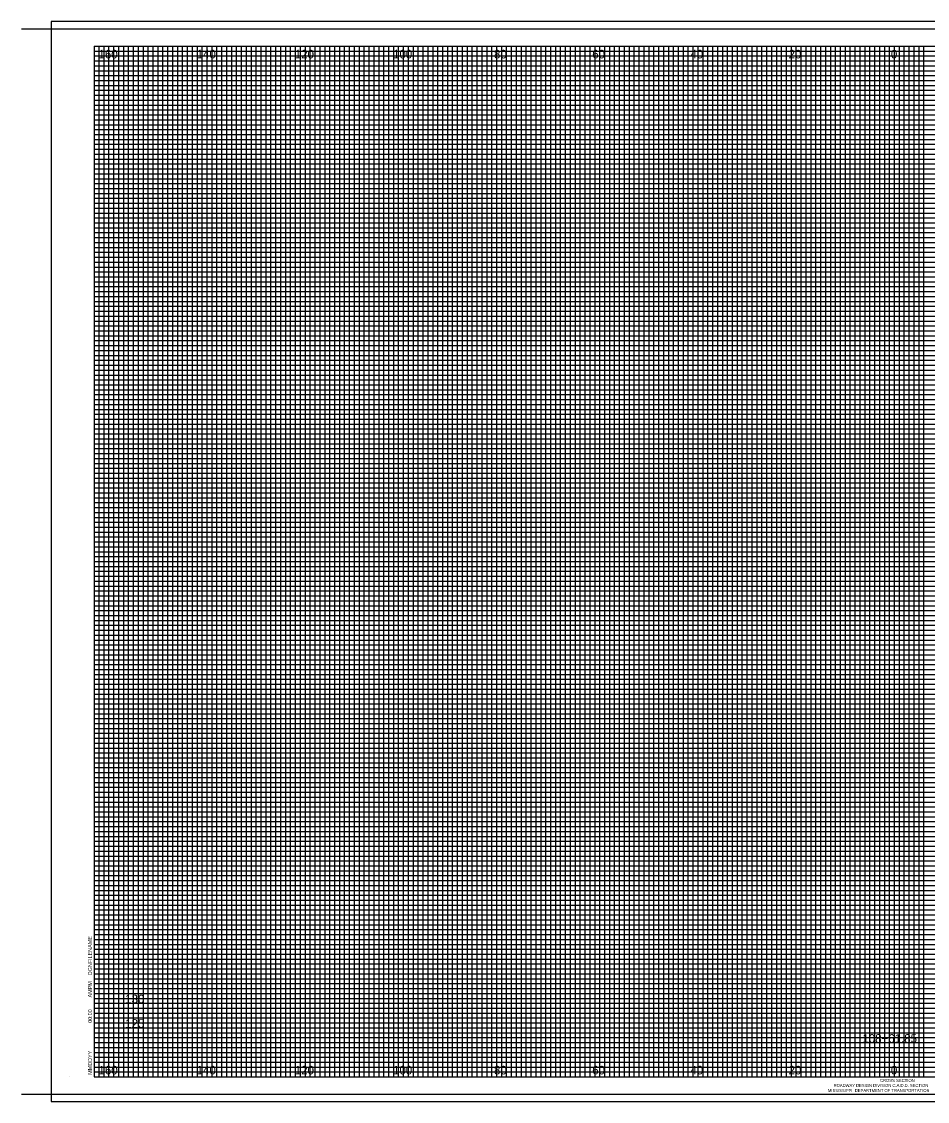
# Model space of a CAD drawing. Extents: x -3604 to 2303, y -13 to 9543.
# Drawn here: x -3604.5 to -3420, y 7604.1 to 7824.1 of the extents above; entities that cross this region are included whole.
import ezdxf

# ---------------------------------------------------------------- set-up
doc = ezdxf.new("R2010")
doc.units = 0
for name, color, linetype in [('SHEET_BORDER', 7, 'Continuous'), ('SHEET_BORDER_TX', 7, 'Continuous'), ('SHEET_DATE_DGN_TX', 7, 'Continuous'), ('SHEET_PLOTTING_SHAPE', 7, 'Continuous'), ('XS_SHEET_LABELS_ELEVATION', 7, 'Continuous'), ('XS_SHEET_LABELS_OFFSET', 7, 'Continuous'), ('XS_SHEET_LABELS_STATION', 7, 'Continuous'), ('XS_SHEET_MAJOR_GRIDS', 7, 'Continuous'), ('XS_SHEET_MEDIUM_GRIDS', 7, 'Continuous'), ('XS_SHEET_MINOR_GRIDS', 7, 'Continuous')]:
    doc.layers.add(name, color=color, linetype=linetype)

msp = doc.modelspace()

# ---------------------------------------------------------------- linework, layer by layer
at = {"layer": 'SHEET_BORDER'}
for p, q in [((-3604.48, 7822.59), (-3252.48, 7822.59)), ((-3589.68, 7819.09), (-3254.68, 7819.09)), ((-3589.68, 7819.09), (-3589.68, 7609.09)), ((-3445.68, 7609.09), (-3445.68, 7819.09)), ((-3594.68, 7609.09), (-3594.68, 7609.09)), ((-3589.68, 7609.09), (-3254.68, 7609.09)), ((-3604.48, 7605.59), (-3252.48, 7605.59))]:
    msp.add_line(p, q, dxfattribs=at)
at = {"layer": 'SHEET_PLOTTING_SHAPE'}
msp.add_lwpolyline([(-3598.48, 7604.09), (-3252.48, 7604.09), (-3252.48, 7824.09), (-3598.48, 7824.09)], close=True, dxfattribs=at)
at = {"layer": 'XS_SHEET_MAJOR_GRIDS'}
for p, q in [((-3584.68, 7609.09), (-3584.68, 7819.09)), ((-3574.68, 7609.09), (-3574.68, 7819.09)), ((-3564.68, 7609.09), (-3564.68, 7819.09)), ((-3554.68, 7609.09), (-3554.68, 7819.09)), ((-3544.68, 7609.09), (-3544.68, 7819.09)), ((-3534.68, 7609.09), (-3534.68, 7819.09)), ((-3524.68, 7609.09), (-3524.68, 7819.09)), ((-3514.68, 7609.09), (-3514.68, 7819.09)), ((-3504.68, 7609.09), (-3504.68, 7819.09)), ((-3494.68, 7609.09), (-3494.68, 7819.09)), ((-3484.68, 7609.09), (-3484.68, 7819.09)), ((-3474.68, 7609.09), (-3474.68, 7819.09)), ((-3464.68, 7609.09), (-3464.68, 7819.09)), ((-3454.68, 7609.09), (-3454.68, 7819.09)), ((-3444.68, 7609.09), (-3444.68, 7819.09)), ((-3434.68, 7609.09), (-3434.68, 7819.09)), ((-3424.68, 7609.09), (-3424.68, 7819.09)), ((-3589.68, 7809.09), (-3254.68, 7809.09)), ((-3589.68, 7799.09), (-3254.68, 7799.09)), ((-3589.68, 7789.09), (-3254.68, 7789.09)), ((-3589.68, 7779.09), (-3254.68, 7779.09)), ((-3589.68, 7769.09), (-3254.68, 7769.09)), ((-3589.68, 7759.09), (-3254.68, 7759.09)), ((-3589.68, 7749.09), (-3254.68, 7749.09)), ((-3589.68, 7739.09), (-3254.68, 7739.09)), ((-3589.68, 7729.09), (-3254.68, 7729.09)), ((-3589.68, 7719.09), (-3254.68, 7719.09)), ((-3589.68, 7709.09), (-3254.68, 7709.09)), ((-3589.68, 7699.09), (-3254.68, 7699.09)), ((-3589.68, 7689.09), (-3254.68, 7689.09)), ((-3589.68, 7679.09), (-3254.68, 7679.09)), ((-3589.68, 7669.09), (-3254.68, 7669.09)), ((-3589.68, 7659.09), (-3254.68, 7659.09)), ((-3589.68, 7649.09), (-3254.68, 7649.09)), ((-3589.68, 7639.09), (-3254.68, 7639.09)), ((-3589.68, 7629.09), (-3254.68, 7629.09)), ((-3589.68, 7619.09), (-3254.68, 7619.09))]:
    msp.add_line(p, q, dxfattribs=at)
at = {"layer": 'XS_SHEET_MEDIUM_GRIDS'}
for p, q in [((-3579.68, 7609.09), (-3579.68, 7819.09)), ((-3569.68, 7609.09), (-3569.68, 7819.09)), ((-3559.68, 7609.09), (-3559.68, 7819.09)), ((-3549.68, 7609.09), (-3549.68, 7819.09)), ((-3539.68, 7609.09), (-3539.68, 7819.09)), ((-3529.68, 7609.09), (-3529.68, 7819.09)), ((-3519.68, 7609.09), (-3519.68, 7819.09)), ((-3509.68, 7609.09), (-3509.68, 7819.09)), ((-3499.68, 7609.09), (-3499.68, 7819.09)), ((-3489.68, 7609.09), (-3489.68, 7819.09)), ((-3479.68, 7609.09), (-3479.68, 7819.09)), ((-3469.68, 7609.09), (-3469.68, 7819.09)), ((-3459.68, 7609.09), (-3459.68, 7819.09)), ((-3449.68, 7609.09), (-3449.68, 7819.09)), ((-3439.68, 7609.09), (-3439.68, 7819.09)), ((-3429.68, 7609.09), (-3429.68, 7819.09)), ((-3589.68, 7814.09), (-3281.68, 7814.09)), ((-3589.68, 7804.09), (-3254.68, 7804.09)), ((-3589.68, 7794.09), (-3254.68, 7794.09)), ((-3589.68, 7784.09), (-3254.68, 7784.09)), ((-3589.68, 7774.09), (-3254.68, 7774.09)), ((-3589.68, 7764.09), (-3254.68, 7764.09)), ((-3589.68, 7754.09), (-3254.68, 7754.09)), ((-3589.68, 7744.09), (-3254.68, 7744.09)), ((-3589.68, 7734.09), (-3254.68, 7734.09)), ((-3589.68, 7724.09), (-3254.68, 7724.09)), ((-3589.68, 7714.09), (-3254.68, 7714.09)), ((-3589.68, 7704.09), (-3254.68, 7704.09)), ((-3589.68, 7694.09), (-3254.68, 7694.09)), ((-3589.68, 7684.09), (-3254.68, 7684.09)), ((-3589.68, 7674.09), (-3254.68, 7674.09)), ((-3589.68, 7664.09), (-3254.68, 7664.09)), ((-3589.68, 7654.09), (-3254.68, 7654.09)), ((-3589.68, 7644.09), (-3254.68, 7644.09)), ((-3589.68, 7634.09), (-3254.68, 7634.09)), ((-3589.68, 7624.09), (-3254.68, 7624.09)), ((-3589.68, 7614.09), (-3264.68, 7614.09))]:
    msp.add_line(p, q, dxfattribs=at)
at = {"layer": 'XS_SHEET_MINOR_GRIDS'}
for p, q in [((-3588.68, 7609.09), (-3588.68, 7819.09)), ((-3587.68, 7609.09), (-3587.68, 7819.09)), ((-3586.68, 7609.09), (-3586.68, 7819.09)), ((-3585.68, 7609.09), (-3585.68, 7819.09)), ((-3583.68, 7609.09), (-3583.68, 7819.09)), ((-3582.68, 7609.09), (-3582.68, 7819.09)), ((-3581.68, 7609.09), (-3581.68, 7819.09)), ((-3580.68, 7609.09), (-3580.68, 7819.09)), ((-3578.68, 7609.09), (-3578.68, 7819.09)), ((-3577.68, 7609.09), (-3577.68, 7819.09)), ((-3576.68, 7609.09), (-3576.68, 7819.09)), ((-3575.68, 7609.09), (-3575.68, 7819.09)), ((-3573.68, 7609.09), (-3573.68, 7819.09)), ((-3572.68, 7609.09), (-3572.68, 7819.09)), ((-3571.68, 7609.09), (-3571.68, 7819.09)), ((-3570.68, 7609.09), (-3570.68, 7819.09)), ((-3568.68, 7609.09), (-3568.68, 7819.09)), ((-3567.68, 7609.09), (-3567.68, 7819.09)), ((-3566.68, 7609.09), (-3566.68, 7819.09)), ((-3565.68, 7609.09), (-3565.68, 7819.09)), ((-3563.68, 7609.09), (-3563.68, 7819.09)), ((-3562.68, 7609.09), (-3562.68, 7819.09)), ((-3561.68, 7609.09), (-3561.68, 7819.09)), ((-3560.68, 7609.09), (-3560.68, 7819.09)), ((-3558.68, 7609.09), (-3558.68, 7819.09)), ((-3557.68, 7609.09), (-3557.68, 7819.09)), ((-3556.68, 7609.09), (-3556.68, 7819.09)), ((-3555.68, 7609.09), (-3555.68, 7819.09)), ((-3553.68, 7609.09), (-3553.68, 7819.09)), ((-3552.68, 7609.09), (-3552.68, 7819.09)), ((-3551.68, 7609.09), (-3551.68, 7819.09)), ((-3550.68, 7609.09), (-3550.68, 7819.09)), ((-3548.68, 7609.09), (-3548.68, 7819.09)), ((-3547.68, 7609.09), (-3547.68, 7819.09)), ((-3546.68, 7609.09), (-3546.68, 7819.09)), ((-3545.68, 7609.09), (-3545.68, 7819.09)), ((-3543.68, 7609.09), (-3543.68, 7819.09)), ((-3542.68, 7609.09), (-3542.68, 7819.09)), ((-3541.68, 7609.09), (-3541.68, 7819.09)), ((-3540.68, 7609.09), (-3540.68, 7819.09)), ((-3538.68, 7609.09), (-3538.68, 7819.09)), ((-3537.68, 7609.09), (-3537.68, 7819.09)), ((-3536.68, 7609.09), (-3536.68, 7819.09)), ((-3535.68, 7609.09), (-3535.68, 7819.09)), ((-3533.68, 7609.09), (-3533.68, 7819.09)), ((-3532.68, 7609.09), (-3532.68, 7819.09)), ((-3531.68, 7609.09), (-3531.68, 7819.09)), ((-3530.68, 7609.09), (-3530.68, 7819.09)), ((-3528.68, 7609.09), (-3528.68, 7819.09)), ((-3527.68, 7609.09), (-3527.68, 7819.09)), ((-3526.68, 7609.09), (-3526.68, 7819.09)), ((-3525.68, 7609.09), (-3525.68, 7819.09)), ((-3523.68, 7609.09), (-3523.68, 7819.09)), ((-3522.68, 7609.09), (-3522.68, 7819.09)), ((-3521.68, 7609.09), (-3521.68, 7819.09)), ((-3520.68, 7609.09), (-3520.68, 7819.09)), ((-3518.68, 7609.09), (-3518.68, 7819.09)), ((-3517.68, 7609.09), (-3517.68, 7819.09)), ((-3516.68, 7609.09), (-3516.68, 7819.09)), ((-3515.68, 7609.09), (-3515.68, 7819.09)), ((-3513.68, 7609.09), (-3513.68, 7819.09)), ((-3512.68, 7609.09), (-3512.68, 7819.09)), ((-3511.68, 7609.09), (-3511.68, 7819.09)), ((-3510.68, 7609.09), (-3510.68, 7819.09)), ((-3508.68, 7609.09), (-3508.68, 7819.09)), ((-3507.68, 7609.09), (-3507.68, 7819.09)), ((-3506.68, 7609.09), (-3506.68, 7819.09)), ((-3505.68, 7609.09), (-3505.68, 7819.09)), ((-3503.68, 7609.09), (-3503.68, 7819.09)), ((-3502.68, 7609.09), (-3502.68, 7819.09)), ((-3501.68, 7609.09), (-3501.68, 7819.09)), ((-3500.68, 7609.09), (-3500.68, 7819.09)), ((-3498.68, 7609.09), (-3498.68, 7819.09)), ((-3497.68, 7609.09), (-3497.68, 7819.09)), ((-3496.68, 7609.09), (-3496.68, 7819.09)), ((-3495.68, 7609.09), (-3495.68, 7819.09)), ((-3493.68, 7609.09), (-3493.68, 7819.09)), ((-3492.68, 7609.09), (-3492.68, 7819.09)), ((-3491.68, 7609.09), (-3491.68, 7819.09)), ((-3490.68, 7609.09), (-3490.68, 7819.09)), ((-3488.68, 7609.09), (-3488.68, 7819.09)), ((-3487.68, 7609.09), (-3487.68, 7819.09)), ((-3486.68, 7609.09), (-3486.68, 7819.09)), ((-3485.68, 7609.09), (-3485.68, 7819.09)), ((-3483.68, 7609.09), (-3483.68, 7819.09)), ((-3482.68, 7609.09), (-3482.68, 7819.09)), ((-3481.68, 7609.09), (-3481.68, 7819.09)), ((-3480.68, 7609.09), (-3480.68, 7819.09)), ((-3478.68, 7609.09), (-3478.68, 7819.09)), ((-3477.68, 7609.09), (-3477.68, 7819.09)), ((-3476.68, 7609.09), (-3476.68, 7819.09)), ((-3475.68, 7609.09), (-3475.68, 7819.09)), ((-3473.68, 7609.09), (-3473.68, 7819.09)), ((-3472.68, 7609.09), (-3472.68, 7819.09)), ((-3471.68, 7609.09), (-3471.68, 7819.09)), ((-3470.68, 7609.09), (-3470.68, 7819.09)), ((-3468.68, 7609.09), (-3468.68, 7819.09)), ((-3467.68, 7609.09), (-3467.68, 7819.09)), ((-3466.68, 7609.09), (-3466.68, 7819.09)), ((-3465.68, 7609.09), (-3465.68, 7819.09)), ((-3463.68, 7609.09), (-3463.68, 7819.09)), ((-3462.68, 7609.09), (-3462.68, 7819.09)), ((-3461.68, 7609.09), (-3461.68, 7819.09)), ((-3460.68, 7609.09), (-3460.68, 7819.09)), ((-3458.68, 7609.09), (-3458.68, 7819.09)), ((-3457.68, 7609.09), (-3457.68, 7819.09)), ((-3456.68, 7609.09), (-3456.68, 7819.09)), ((-3455.68, 7609.09), (-3455.68, 7819.09)), ((-3453.68, 7609.09), (-3453.68, 7819.09)), ((-3452.68, 7609.09), (-3452.68, 7819.09)), ((-3451.68, 7609.09), (-3451.68, 7819.09)), ((-3450.68, 7609.09), (-3450.68, 7819.09)), ((-3448.68, 7609.09), (-3448.68, 7819.09)), ((-3447.68, 7609.09), (-3447.68, 7819.09)), ((-3446.68, 7609.09), (-3446.68, 7819.09)), ((-3443.68, 7609.09), (-3443.68, 7819.09)), ((-3442.68, 7609.09), (-3442.68, 7819.09)), ((-3441.68, 7609.09), (-3441.68, 7819.09)), ((-3440.68, 7609.09), (-3440.68, 7819.09)), ((-3438.68, 7609.09), (-3438.68, 7819.09)), ((-3437.68, 7609.09), (-3437.68, 7819.09)), ((-3436.68, 7609.09), (-3436.68, 7819.09)), ((-3435.68, 7609.09), (-3435.68, 7819.09)), ((-3433.68, 7609.09), (-3433.68, 7819.09)), ((-3432.68, 7609.09), (-3432.68, 7819.09)), ((-3431.68, 7609.09), (-3431.68, 7819.09)), ((-3430.68, 7609.09), (-3430.68, 7819.09)), ((-3428.68, 7609.09), (-3428.68, 7819.09)), ((-3427.68, 7609.09), (-3427.68, 7819.09)), ((-3426.68, 7609.09), (-3426.68, 7819.09)), ((-3425.68, 7609.09), (-3425.68, 7819.09)), ((-3423.68, 7609.09), (-3423.68, 7819.09)), ((-3422.68, 7609.09), (-3422.68, 7819.09)), ((-3421.68, 7609.09), (-3421.68, 7819.09)), ((-3420.68, 7609.09), (-3420.68, 7819.09)), ((-3589.68, 7818.09), (-3281.68, 7818.09)), ((-3589.68, 7817.09), (-3281.68, 7817.09)), ((-3589.68, 7816.09), (-3281.68, 7816.09)), ((-3589.68, 7815.09), (-3281.68, 7815.09)), ((-3589.68, 7813.09), (-3281.68, 7813.09)), ((-3589.68, 7812.09), (-3281.68, 7812.09)), ((-3589.68, 7811.09), (-3281.68, 7811.09)), ((-3589.68, 7810.09), (-3254.68, 7810.09)), ((-3589.68, 7808.09), (-3254.68, 7808.09)), ((-3589.68, 7807.09), (-3254.68, 7807.09)), ((-3589.68, 7806.09), (-3254.68, 7806.09)), ((-3589.68, 7805.09), (-3254.68, 7805.09)), ((-3589.68, 7803.09), (-3254.68, 7803.09)), ((-3589.68, 7802.09), (-3254.68, 7802.09)), ((-3589.68, 7801.09), (-3254.68, 7801.09)), ((-3589.68, 7800.09), (-3254.68, 7800.09)), ((-3589.68, 7798.09), (-3254.68, 7798.09)), ((-3589.68, 7797.09), (-3254.68, 7797.09)), ((-3589.68, 7796.09), (-3254.68, 7796.09)), ((-3589.68, 7795.09), (-3254.68, 7795.09)), ((-3589.68, 7793.09), (-3254.68, 7793.09)), ((-3589.68, 7792.09), (-3254.68, 7792.09)), ((-3589.68, 7791.09), (-3254.68, 7791.09)), ((-3589.68, 7790.09), (-3254.68, 7790.09)), ((-3589.68, 7788.09), (-3254.68, 7788.09)), ((-3589.68, 7787.09), (-3254.68, 7787.09)), ((-3589.68, 7786.09), (-3254.68, 7786.09)), ((-3589.68, 7785.09), (-3254.68, 7785.09)), ((-3589.68, 7783.09), (-3254.68, 7783.09)), ((-3589.68, 7782.09), (-3254.68, 7782.09)), ((-3589.68, 7781.09), (-3254.68, 7781.09)), ((-3589.68, 7780.09), (-3254.68, 7780.09)), ((-3589.68, 7778.09), (-3254.68, 7778.09)), ((-3589.68, 7777.09), (-3254.68, 7777.09)), ((-3589.68, 7776.09), (-3254.68, 7776.09)), ((-3589.68, 7775.09), (-3254.68, 7775.09)), ((-3589.68, 7773.09), (-3254.68, 7773.09)), ((-3589.68, 7772.09), (-3254.68, 7772.09)), ((-3589.68, 7771.09), (-3254.68, 7771.09)), ((-3589.68, 7770.09), (-3254.68, 7770.09)), ((-3589.68, 7768.09), (-3254.68, 7768.09)), ((-3589.68, 7767.09), (-3254.68, 7767.09)), ((-3589.68, 7766.09), (-3254.68, 7766.09)), ((-3589.68, 7765.09), (-3254.68, 7765.09)), ((-3589.68, 7763.09), (-3254.68, 7763.09)), ((-3589.68, 7762.09), (-3254.68, 7762.09)), ((-3589.68, 7761.09), (-3254.68, 7761.09)), ((-3589.68, 7760.09), (-3254.68, 7760.09)), ((-3589.68, 7758.09), (-3254.68, 7758.09)), ((-3589.68, 7757.09), (-3254.68, 7757.09)), ((-3589.68, 7756.09), (-3254.68, 7756.09)), ((-3589.68, 7755.09), (-3254.68, 7755.09)), ((-3589.68, 7753.09), (-3254.68, 7753.09)), ((-3589.68, 7752.09), (-3254.68, 7752.09)), ((-3589.68, 7751.09), (-3254.68, 7751.09)), ((-3589.68, 7750.09), (-3254.68, 7750.09)), ((-3589.68, 7748.09), (-3254.68, 7748.09)), ((-3589.68, 7747.09), (-3254.68, 7747.09)), ((-3589.68, 7746.09), (-3254.68, 7746.09)), ((-3589.68, 7745.09), (-3254.68, 7745.09)), ((-3589.68, 7743.09), (-3254.68, 7743.09)), ((-3589.68, 7742.09), (-3254.68, 7742.09)), ((-3589.68, 7741.09), (-3254.68, 7741.09)), ((-3589.68, 7740.09), (-3254.68, 7740.09)), ((-3589.68, 7738.09), (-3254.68, 7738.09)), ((-3589.68, 7737.09), (-3254.68, 7737.09)), ((-3589.68, 7736.09), (-3254.68, 7736.09)), ((-3589.68, 7735.09), (-3254.68, 7735.09)), ((-3589.68, 7733.09), (-3254.68, 7733.09)), ((-3589.68, 7732.09), (-3254.68, 7732.09)), ((-3589.68, 7731.09), (-3254.68, 7731.09)), ((-3589.68, 7730.09), (-3254.68, 7730.09)), ((-3589.68, 7728.09), (-3254.68, 7728.09)), ((-3589.68, 7727.09), (-3254.68, 7727.09)), ((-3589.68, 7726.09), (-3254.68, 7726.09)), ((-3589.68, 7725.09), (-3254.68, 7725.09)), ((-3589.68, 7723.09), (-3254.68, 7723.09)), ((-3589.68, 7722.09), (-3254.68, 7722.09)), ((-3589.68, 7721.09), (-3254.68, 7721.09)), ((-3589.68, 7720.09), (-3254.68, 7720.09)), ((-3589.68, 7718.09), (-3254.68, 7718.09)), ((-3589.68, 7717.09), (-3254.68, 7717.09)), ((-3589.68, 7716.09), (-3254.68, 7716.09)), ((-3589.68, 7715.09), (-3254.68, 7715.09)), ((-3589.68, 7713.09), (-3254.68, 7713.09)), ((-3589.68, 7712.09), (-3254.68, 7712.09)), ((-3589.68, 7711.09), (-3254.68, 7711.09)), ((-3589.68, 7710.09), (-3254.68, 7710.09)), ((-3589.68, 7708.09), (-3254.68, 7708.09)), ((-3589.68, 7707.09), (-3254.68, 7707.09)), ((-3589.68, 7706.09), (-3254.68, 7706.09)), ((-3589.68, 7705.09), (-3254.68, 7705.09)), ((-3589.68, 7703.09), (-3254.68, 7703.09)), ((-3589.68, 7702.09), (-3254.68, 7702.09)), ((-3589.68, 7701.09), (-3254.68, 7701.09)), ((-3589.68, 7700.09), (-3254.68, 7700.09)), ((-3589.68, 7698.09), (-3254.68, 7698.09)), ((-3589.68, 7697.09), (-3254.68, 7697.09)), ((-3589.68, 7696.09), (-3254.68, 7696.09)), ((-3589.68, 7695.09), (-3254.68, 7695.09)), ((-3589.68, 7693.09), (-3254.68, 7693.09)), ((-3589.68, 7692.09), (-3254.68, 7692.09)), ((-3589.68, 7691.09), (-3254.68, 7691.09)), ((-3589.68, 7690.09), (-3254.68, 7690.09)), ((-3589.68, 7688.09), (-3254.68, 7688.09)), ((-3589.68, 7687.09), (-3254.68, 7687.09)), ((-3589.68, 7686.09), (-3254.68, 7686.09)), ((-3589.68, 7685.09), (-3254.68, 7685.09)), ((-3589.68, 7683.09), (-3254.68, 7683.09)), ((-3589.68, 7682.09), (-3254.68, 7682.09)), ((-3589.68, 7681.09), (-3254.68, 7681.09)), ((-3589.68, 7680.09), (-3254.68, 7680.09)), ((-3589.68, 7678.09), (-3254.68, 7678.09)), ((-3589.68, 7677.09), (-3254.68, 7677.09)), ((-3589.68, 7676.09), (-3254.68, 7676.09)), ((-3589.68, 7675.09), (-3254.68, 7675.09)), ((-3589.68, 7673.09), (-3254.68, 7673.09)), ((-3589.68, 7672.09), (-3254.68, 7672.09)), ((-3589.68, 7671.09), (-3254.68, 7671.09)), ((-3589.68, 7670.09), (-3254.68, 7670.09)), ((-3589.68, 7668.09), (-3254.68, 7668.09)), ((-3589.68, 7667.09), (-3254.68, 7667.09)), ((-3589.68, 7666.09), (-3254.68, 7666.09)), ((-3589.68, 7665.09), (-3254.68, 7665.09)), ((-3589.68, 7663.09), (-3254.68, 7663.09)), ((-3589.68, 7662.09), (-3254.68, 7662.09)), ((-3589.68, 7661.09), (-3254.68, 7661.09)), ((-3589.68, 7660.09), (-3254.68, 7660.09)), ((-3589.68, 7658.09), (-3254.68, 7658.09)), ((-3589.68, 7657.09), (-3254.68, 7657.09)), ((-3589.68, 7656.09), (-3254.68, 7656.09)), ((-3589.68, 7655.09), (-3254.68, 7655.09)), ((-3589.68, 7653.09), (-3254.68, 7653.09)), ((-3589.68, 7652.09), (-3254.68, 7652.09)), ((-3589.68, 7651.09), (-3254.68, 7651.09)), ((-3589.68, 7650.09), (-3254.68, 7650.09)), ((-3589.68, 7648.09), (-3254.68, 7648.09)), ((-3589.68, 7647.09), (-3254.68, 7647.09)), ((-3589.68, 7646.09), (-3254.68, 7646.09)), ((-3589.68, 7645.09), (-3254.68, 7645.09)), ((-3589.68, 7643.09), (-3254.68, 7643.09)), ((-3589.68, 7642.09), (-3254.68, 7642.09)), ((-3589.68, 7641.09), (-3254.68, 7641.09)), ((-3589.68, 7640.09), (-3254.68, 7640.09)), ((-3589.68, 7638.09), (-3254.68, 7638.09)), ((-3589.68, 7637.09), (-3254.68, 7637.09)), ((-3589.68, 7636.09), (-3254.68, 7636.09)), ((-3589.68, 7635.09), (-3254.68, 7635.09)), ((-3589.68, 7633.09), (-3254.68, 7633.09)), ((-3589.68, 7632.09), (-3254.68, 7632.09)), ((-3589.68, 7631.09), (-3254.68, 7631.09)), ((-3589.68, 7630.09), (-3254.68, 7630.09)), ((-3589.68, 7630.09), (-3254.68, 7630.09)), ((-3589.68, 7630.09), (-3254.68, 7630.09)), ((-3589.68, 7628.09), (-3254.68, 7628.09)), ((-3589.68, 7627.09), (-3254.68, 7627.09)), ((-3589.68, 7626.09), (-3254.68, 7626.09)), ((-3589.68, 7625.09), (-3254.68, 7625.09)), ((-3589.68, 7623.09), (-3254.68, 7623.09)), ((-3589.68, 7622.09), (-3254.68, 7622.09)), ((-3589.68, 7621.09), (-3254.68, 7621.09)), ((-3589.68, 7620.09), (-3254.68, 7620.09)), ((-3589.68, 7618.09), (-3264.68, 7618.09)), ((-3589.68, 7617.09), (-3264.68, 7617.09)), ((-3589.68, 7616.09), (-3264.68, 7616.09)), ((-3589.68, 7615.09), (-3264.68, 7615.09)), ((-3589.68, 7615.09), (-3264.68, 7615.09)), ((-3589.68, 7615.09), (-3264.68, 7615.09)), ((-3589.68, 7613.09), (-3264.68, 7613.09)), ((-3589.68, 7612.09), (-3264.68, 7612.09)), ((-3589.68, 7611.09), (-3264.68, 7611.09)), ((-3589.68, 7610.09), (-3264.68, 7610.09))]:
    msp.add_line(p, q, dxfattribs=at)

# ---------------------------------------------------------------- texts
at = {"layer": 'SHEET_BORDER_TX'}
for s, height, p in [('ROADWAY DESIGN DIVISION C.A.D.D. SECTION', 0.61, (-3439.08, 7607.04)), ('CROSS SECTION', 0.62, (-3429.64, 7608.06)), ('MISSISSIPPI  DEPARTMENT OF TRANSPORTATION', 0.61, (-3440.24, 7606.01))]:
    msp.add_text(s, height=height, dxfattribs=at).set_placement(p)
at = {"layer": 'SHEET_DATE_DGN_TX'}
for s, p in [('DGNFILENAME', (-3590.15, 7629.79)), ('AMPM', (-3590.15, 7625.27)), ('00:00', (-3590.15, 7620.09)), ('MMDDYY', (-3590.15, 7609.51))]:
    msp.add_text(s, height=0.8, rotation=90, dxfattribs=at).set_placement(p)
at = {"layer": 'XS_SHEET_LABELS_ELEVATION'}
for s, p in [('  130  ', (-3584.68, 7624.09)), ('  125  ', (-3584.68, 7619.09))]:
    msp.add_text(s, height=1.75, dxfattribs=at).set_placement(p)
at = {"layer": 'XS_SHEET_LABELS_OFFSET'}
for s, p in [('  160  ', (-3590.11, 7816.59)), ('  140  ', (-3570.13, 7816.59)), ('  120  ', (-3550.13, 7816.59)), ('  100  ', (-3530.13, 7816.59)), ('  80  ', (-3509.56, 7816.59)), ('  60  ', (-3489.55, 7816.59)), ('  40  ', (-3469.56, 7816.59)), ('  20  ', (-3449.56, 7816.59)), ('  0  ', (-3428.71, 7816.59)), ('  0  ', (-3428.71, 7816.59)), ('  160  ', (-3590.11, 7609.59)), ('  140  ', (-3570.13, 7609.59)), ('  120  ', (-3550.13, 7609.59)), ('  100  ', (-3530.13, 7609.59)), ('  80  ', (-3509.56, 7609.59)), ('  60  ', (-3489.55, 7609.59)), ('  40  ', (-3469.56, 7609.59)), ('  20  ', (-3449.56, 7609.59)), ('  0  ', (-3428.71, 7609.59)), ('  0  ', (-3428.71, 7609.59))]:
    msp.add_text(s, height=1.75, dxfattribs=at).set_placement(p)
at = {"layer": 'XS_SHEET_LABELS_STATION'}
msp.add_text('  108+61.85  ', height=1.75, dxfattribs=at).set_placement((-3434.52, 7616.04))

doc.saveas('drawing.dxf')
